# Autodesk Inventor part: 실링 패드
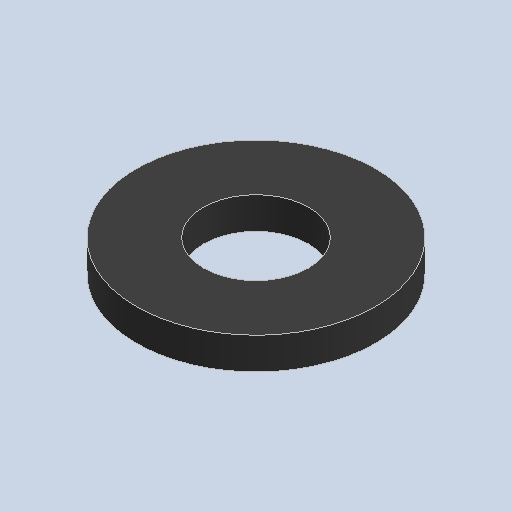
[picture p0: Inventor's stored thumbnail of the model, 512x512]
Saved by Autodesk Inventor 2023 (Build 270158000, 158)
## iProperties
Created: 2024-09
Part Number: 실링 패드
Material: 고무
Document SubType Name: Modeling
Designer: home
Density: 0.93 g/cm^3
Appearance: 기본값
Author: jhkim
Sending System: Autodesk Inventor 2025
Preprocessor: ST-DEVELOPER v20
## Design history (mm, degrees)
node "실링 패드1"
node "솔리드2"
node "솔리드1"
